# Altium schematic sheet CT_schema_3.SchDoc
size 430 x 414 mm
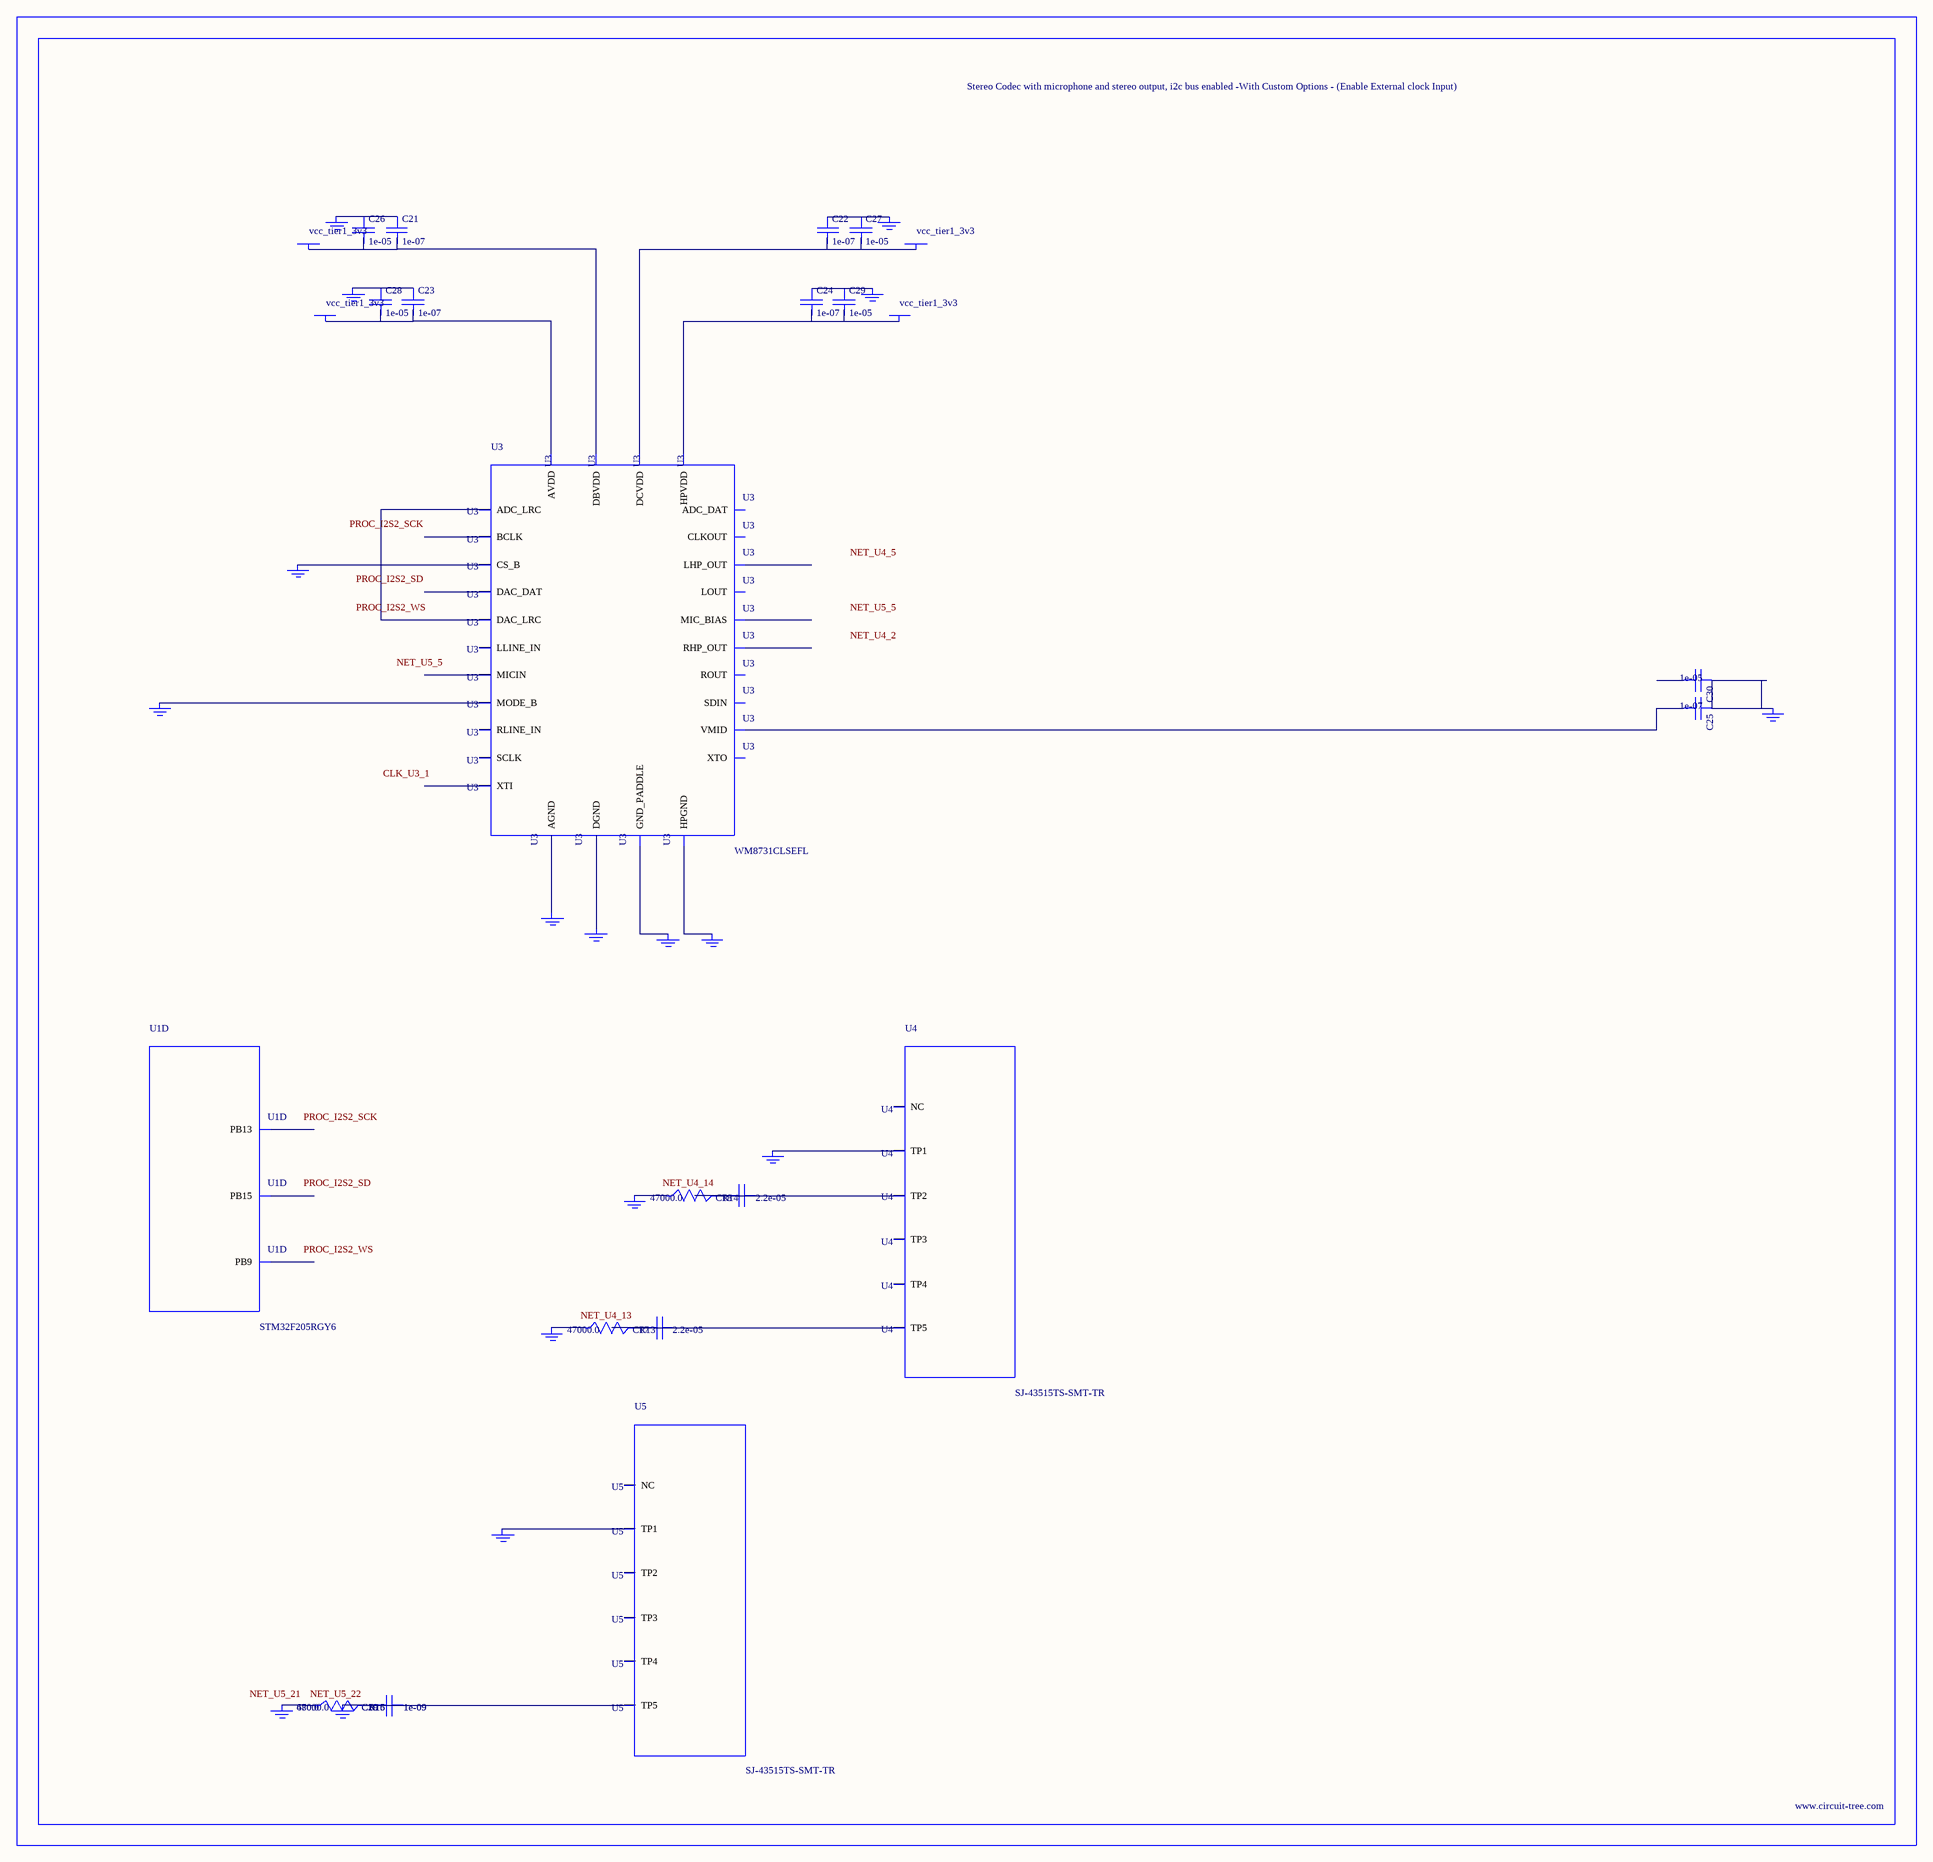
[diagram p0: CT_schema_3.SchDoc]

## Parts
BORDER2  (no value)
C17  2.2e-05  [C1210]
C18  2.2e-05  [C1210]
C19  1e-09  [C0402]
C20  1e-09  [C0402]
C21  1e-07  [C0402]
C22  1e-07  [C0402]
C23  1e-07  [C0402]
C24  1e-07  [C0402]
C25  1e-07  [C0402]
C26  1e-05  [C0805]
C27  1e-05  [C0805]
C28  1e-05  [C0805]
C29  1e-05  [C0805]
C30  1e-05  [C0805]
GND_INSTANCE_2_0  (no value)
GND_INSTANCE_2_1  (no value)
GND_INSTANCE_2_2  (no value)
GND_INSTANCE_2_3  (no value)
GND_INSTANCE_2_4  (no value)
GND_INSTANCE_2_5  (no value)
GND_INSTANCE_2_6  (no value)
GND_INSTANCE_2_7  (no value)
GND_INSTANCE_2_8  (no value)
GND_INSTANCE_2_9  (no value)
GND_INSTANCE_2_10  (no value)
GND_INSTANCE_2_11  (no value)
GND_INSTANCE_2_12  (no value)
GND_INSTANCE_2_13  (no value)
GND_INSTANCE_2_14  (no value)
GND_INSTANCE_2_15  (no value)
GND_INSTANCE_2_16  (no value)
POWER_INSTANCE_2_0  vcc_tier1_3v3
POWER_INSTANCE_2_1  vcc_tier1_3v3
POWER_INSTANCE_2_2  vcc_tier1_3v3
POWER_INSTANCE_2_3  vcc_tier1_3v3
R13  47000.0  [R0603]
R14  47000.0  [R0603]
R15  47000.0  [R0603]
R16  680.0  [R0603]
U1  STM32F205RGY6  [WLCSP66]  (part D of 6)
U3  WM8731CLSEFL  [QFN-28]
U4  SJ-43515TS-SMT-TR  [SJ-43515TS-SMT-TR]
U5  SJ-43515TS-SMT-TR  [SJ-43515TS-SMT-TR]

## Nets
NetC17_1: C17.1 C17.2 R13.2 U4.5(TP5)
NetC18_1: C18.1 C18.2 R14.2 U4.2(TP2)
NetC19_1: C19.1 C19.2 C20.1 C20.2 GND_INSTANCE_2_16.0(GND) R15.2 R16.2 U5.5(TP5)
NetC21_1: C21.1 C26.1 GND_INSTANCE_2_1.0(GND)
NetC21_2: C21.2 C26.2 POWER_INSTANCE_2_1.0(PWR) U3.5(DBVDD)
NetC22_1: C22.1 C27.1 GND_INSTANCE_2_0.0(GND)
NetC22_2: C22.2 C27.2 POWER_INSTANCE_2_0.0(PWR) U3.3(DCVDD)
NetC23_1: C23.1 C28.1 GND_INSTANCE_2_4.0(GND)
NetC23_2: C23.2 C28.2 POWER_INSTANCE_2_3.0(PWR) U3.18(AVDD)
NetC24_1: C24.1 C29.1 GND_INSTANCE_2_2.0(GND)
NetC24_2: C24.2 C29.2 POWER_INSTANCE_2_2.0(PWR) U3.12(HPVDD)
NetC25_1: C25.1 C30.1 GND_INSTANCE_2_5.0(GND)
NetC25_2: C25.2 U3.20(VMID)
NetGND_INSTANCE_2_3_0: GND_INSTANCE_2_3.0(GND) U3.15(HPGND)
NetGND_INSTANCE_2_6_0: GND_INSTANCE_2_6.0(GND) U3.25(MODE_B)
NetGND_INSTANCE_2_7_0: GND_INSTANCE_2_7.0(GND) U3.26(CS_B)
NetGND_INSTANCE_2_8_0: GND_INSTANCE_2_8.0(GND) U3.29(GND_PADDLE)
NetGND_INSTANCE_2_9_0: GND_INSTANCE_2_9.0(GND) U3.4(DGND)
NetGND_INSTANCE_2_10_0: GND_INSTANCE_2_10.0(GND) U3.19(AGND)
NetGND_INSTANCE_2_11_0: GND_INSTANCE_2_11.0(GND) U4.1(TP1)
NetGND_INSTANCE_2_12_0: GND_INSTANCE_2_12.0(GND) R14.1
NetGND_INSTANCE_2_13_0: GND_INSTANCE_2_13.0(GND) R13.1
NetGND_INSTANCE_2_14_0: GND_INSTANCE_2_14.0(GND) U5.1(TP1)
NetGND_INSTANCE_2_15_0: GND_INSTANCE_2_15.0(GND) R15.1 R16.1
NetU3_9: U3.9(DAC_LRC) U3.11(ADC_LRC)

Not connected (* = marked no-connect by the designer): C30 2; U1 A7(PB9) G1(PB15) H2(PB13); U3 1(XTI) 2(XTO) 6(CLKOUT) 7(BCLK) 8(DAC_DAT) 10(ADC_DAT) 13(LHP_OUT) 14(RHP_OUT) 16(LOUT) 17(ROUT) 21(MIC_BIAS) 22(MICIN) 23(RLINE_IN) 24(LLINE_IN) 27(SDIN) 28(SCLK); U4 3(TP3) 4(TP4) 6(NC); U5 2(TP2) 3(TP3) 4(TP4) 6(NC)

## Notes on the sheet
- Labels drawn without touching a wire or pin: CLK_U3_1, NET_U4_2, NET_U4_5, NET_U4_13, NET_U4_14, NET_U5_5, NET_U5_21, NET_U5_22, PROC_I2S2_SCK, PROC_I2S2_SD, PROC_I2S2_WS

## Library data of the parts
BORDER2 = BORDER_PAGE2
C17 C18 = C1210C224K5RACTU
C19 C20 = C0402C102K3RAC
C21-C25 = C0402C104K3RACTU
C26-C30 = C0805C106K8RACTU
GND_INSTANCE_2_0-GND_INSTANCE_2_16 = GND
POWER_INSTANCE_2_0-POWER_INSTANCE_2_3 = PWR
R13-R15 = RC0603JR-0747KL
R16 = RC0603JR-07680RL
